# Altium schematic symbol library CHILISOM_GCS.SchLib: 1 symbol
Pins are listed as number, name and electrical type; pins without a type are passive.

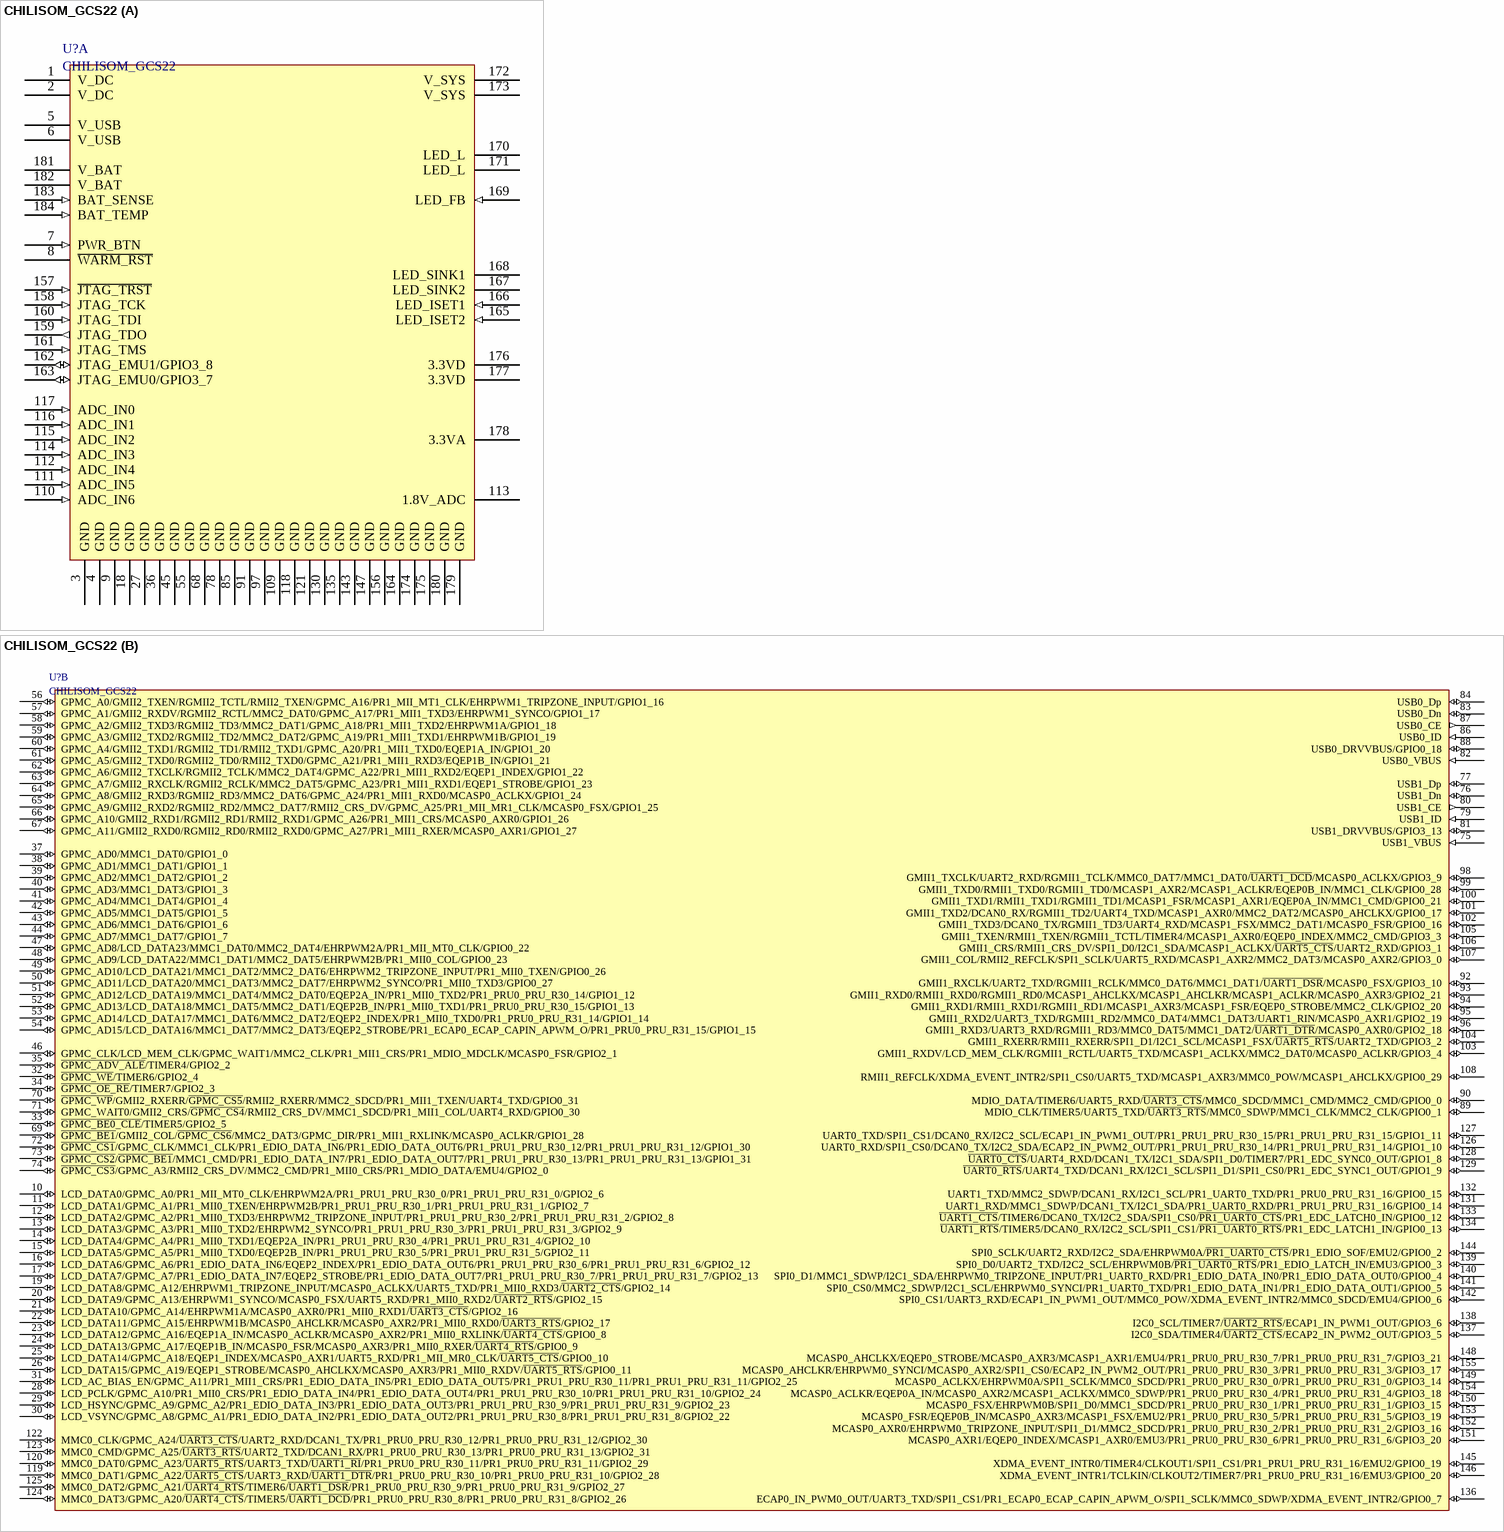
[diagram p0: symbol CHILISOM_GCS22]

## CHILISOM_GCS22
designator U?
footprint CHILISOM_GCS22 (Footprint not found)
part A pins: 1 V_DC (power), 2 V_DC (power), 3 GND (power), 4 GND (power), 5 V_USB (power), 6 V_USB (power), 7 PWR_BTN (in), 8 ~{WARM_RST} (oc), 9 GND (power), 18 GND (power), 27 GND (power), 36 GND (power), 45 GND (power), 55 GND (power), 68 GND (power), 78 GND (power), 85 GND (power), 91 GND (power), 97 GND (power), 109 GND (power), 110 ADC_IN6 (in), 111 ADC_IN5 (in), 112 ADC_IN4 (in), 113 1.8V_ADC (power), 114 ADC_IN3 (in), 115 ADC_IN2 (in), 116 ADC_IN1 (in), 117 ADC_IN0 (in), 118 GND (power), 121 GND (power), 130 GND (power), 135 GND (power), 143 GND (power), 147 GND (power), 156 GND (power), 157 ~{JTAG_TRST} (in), 158 JTAG_TCK (in), 159 JTAG_TDO (out), 160 JTAG_TDI (in), 161 JTAG_TMS (in), 162 JTAG_EMU1/GPIO3_8 (io), 163 JTAG_EMU0/GPIO3_7 (io), 164 GND (power), 165 LED_ISET2 (in), 166 LED_ISET1 (in), 167 LED_SINK2, 168 LED_SINK1, 169 LED_FB (in), 170 LED_L, 171 LED_L, 172 V_SYS (power), 173 V_SYS (power), 174 GND (power), 175 GND (power), 176 3.3VD (power), 177 3.3VD (power), 178 3.3VA (power), 179 GND (power), 180 GND (power), 181 V_BAT (power), 182 V_BAT (power), 183 BAT_SENSE (in), 184 BAT_TEMP (in)
part B pins: 10 LCD_DATA0/GPMC_A0/PR1_MII_MT0_CLK/EHRPWM2A/PR1_PRU1_PRU_R30_0/PR1_PRU1_PRU_R31_0/GPIO2_6 (io), 11 LCD_DATA1/GPMC_A1/PR1_MII0_TXEN/EHRPWM2B/PR1_PRU1_PRU_R30_1/PR1_PRU1_PRU_R31_1/GPIO2_7 (io), 12 LCD_DATA2/GPMC_A2/PR1_MII0_TXD3/EHRPWM2_TRIPZONE_INPUT/PR1_PRU1_PRU_R30_2/PR1_PRU1_PRU_R31_2/GPIO2_8 (io), 13 LCD_DATA3/GPMC_A3/PR1_MII0_TXD2/EHRPWM2_SYNCO/PR1_PRU1_PRU_R30_3/PR1_PRU1_PRU_R31_3/GPIO2_9 (io), 14 LCD_DATA4/GPMC_A4/PR1_MII0_TXD1/EQEP2A_IN/PR1_PRU1_PRU_R30_4/PR1_PRU1_PRU_R31_4/GPIO2_10 (io), 15 LCD_DATA5/GPMC_A5/PR1_MII0_TXD0/EQEP2B_IN/PR1_PRU1_PRU_R30_5/PR1_PRU1_PRU_R31_5/GPIO2_11 (io), 16 LCD_DATA6/GPMC_A6/PR1_EDIO_DATA_IN6/EQEP2_INDEX/PR1_EDIO_DATA_OUT6/PR1_PRU1_PRU_R30_6/PR1_PRU1_PRU_R31_6/GPIO2_12 (io), 17 LCD_DATA7/GPMC_A7/PR1_EDIO_DATA_IN7/EQEP2_STROBE/PR1_EDIO_DATA_OUT7/PR1_PRU1_PRU_R30_7/PR1_PRU1_PRU_R31_7/GPIO2_13 (io), 19 LCD_DATA8/GPMC_A12/EHRPWM1_TRIPZONE_INPUT/MCASP0_ACLKX/UART5_TXD/PR1_MII0_RXD3/~{UART2_CTS}/GPIO2_14 (io), 20 LCD_DATA9/GPMC_A13/EHRPWM1_SYNCO/MCASP0_FSX/UART5_RXD/PR1_MII0_RXD2/~{UART2_RTS}/GPIO2_15 (io), 21 LCD_DATA10/GPMC_A14/EHRPWM1A/MCASP0_AXR0/PR1_MII0_RXD1/~{UART3_CTS}/GPIO2_16 (io), 22 LCD_DATA11/GPMC_A15/EHRPWM1B/MCASP0_AHCLKR/MCASP0_AXR2/PR1_MII0_RXD0/~{UART3_RTS}/GPIO2_17 (io), 23 LCD_DATA12/GPMC_A16/EQEP1A_IN/MCASP0_ACLKR/MCASP0_AXR2/PR1_MII0_RXLINK/~{UART4_CTS}/GPIO0_8 (io), 24 LCD_DATA13/GPMC_A17/EQEP1B_IN/MCASP0_FSR/MCASP0_AXR3/PR1_MII0_RXER/~{UART4_RTS}/GPIO0_9 (io), 25 LCD_DATA14/GPMC_A18/EQEP1_INDEX/MCASP0_AXR1/UART5_RXD/PR1_MII_MR0_CLK/~{UART5_CTS}/GPIO0_10 (io), 26 LCD_DATA15/GPMC_A19/EQEP1_STROBE/MCASP0_AHCLKX/MCASP0_AXR3/PR1_MII0_RXDV/~{UART5_RTS}/GPIO0_11 (io), 28 LCD_PCLK/GPMC_A10/PR1_MII0_CRS/PR1_EDIO_DATA_IN4/PR1_EDIO_DATA_OUT4/PR1_PRU1_PRU_R30_10/PR1_PRU1_PRU_R31_10/GPIO2_24 (io), 29 LCD_HSYNC/GPMC_A9/GPMC_A2/PR1_EDIO_DATA_IN3/PR1_EDIO_DATA_OUT3/PR1_PRU1_PRU_R30_9/PR1_PRU1_PRU_R31_9/GPIO2_23 (io), 30 LCD_VSYNC/GPMC_A8/GPMC_A1/PR1_EDIO_DATA_IN2/PR1_EDIO_DATA_OUT2/PR1_PRU1_PRU_R30_8/PR1_PRU1_PRU_R31_8/GPIO2_22 (io), 31 LCD_AC_BIAS_EN/GPMC_A11/PR1_MII1_CRS/PR1_EDIO_DATA_IN5/PR1_EDIO_DATA_OUT5/PR1_PRU1_PRU_R30_11/PR1_PRU1_PRU_R31_11/GPIO2_25 (io), 32 ~{GPMC_WE}/TIMER6/GPIO2_4 (io), 33 ~{GPMC_BE0_CLE}/TIMER5/GPIO2_5 (io), 34 ~{GPMC_OE_RE}/TIMER7/GPIO2_3 (io), 35 ~{GPMC_ADV_ALE}/TIMER4/GPIO2_2 (io), 37 GPMC_AD0/MMC1_DAT0/GPIO1_0 (io), 38 GPMC_AD1/MMC1_DAT1/GPIO1_1 (io), 39 GPMC_AD2/MMC1_DAT2/GPIO1_2 (io), 40 GPMC_AD3/MMC1_DAT3/GPIO1_3 (io), 41 GPMC_AD4/MMC1_DAT4/GPIO1_4 (io), 42 GPMC_AD5/MMC1_DAT5/GPIO1_5 (io), 43 GPMC_AD6/MMC1_DAT6/GPIO1_6 (io), 44 GPMC_AD7/MMC1_DAT7/GPIO1_7 (io), 46 GPMC_CLK/LCD_MEM_CLK/GPMC_WAIT1/MMC2_CLK/PR1_MII1_CRS/PR1_MDIO_MDCLK/MCASP0_FSR/GPIO2_1 (io), 47 GPMC_AD8/LCD_DATA23/MMC1_DAT0/MMC2_DAT4/EHRPWM2A/PR1_MII_MT0_CLK/GPIO0_22 (io), 48 GPMC_AD9/LCD_DATA22/MMC1_DAT1/MMC2_DAT5/EHRPWM2B/PR1_MII0_COL/GPIO0_23 (io), 49 GPMC_AD10/LCD_DATA21/MMC1_DAT2/MMC2_DAT6/EHRPWM2_TRIPZONE_INPUT/PR1_MII0_TXEN/GPIO0_26 (io), 50 GPMC_AD11/LCD_DATA20/MMC1_DAT3/MMC2_DAT7/EHRPWM2_SYNCO/PR1_MII0_TXD3/GPIO0_27 (io), 51 GPMC_AD12/LCD_DATA19/MMC1_DAT4/MMC2_DAT0/EQEP2A_IN/PR1_MII0_TXD2/PR1_PRU0_PRU_R30_14/GPIO1_12 (io), 52 GPMC_AD13/LCD_DATA18/MMC1_DAT5/MMC2_DAT1/EQEP2B_IN/PR1_MII0_TXD1/PR1_PRU0_PRU_R30_15/GPIO1_13 (io), 53 GPMC_AD14/LCD_DATA17/MMC1_DAT6/MMC2_DAT2/EQEP2_INDEX/PR1_MII0_TXD0/PR1_PRU0_PRU_R31_14/GPIO1_14 (io), 54 GPMC_AD15/LCD_DATA16/MMC1_DAT7/MMC2_DAT3/EQEP2_STROBE/PR1_ECAP0_ECAP_CAPIN_APWM_O/PR1_PRU0_PRU_R31_15/GPIO1_15 (io), 56 GPMC_A0/GMII2_TXEN/RGMII2_TCTL/RMII2_TXEN/GPMC_A16/PR1_MII_MT1_CLK/EHRPWM1_TRIPZONE_INPUT/GPIO1_16 (io), 57 GPMC_A1/GMII2_RXDV/RGMII2_RCTL/MMC2_DAT0/GPMC_A17/PR1_MII1_TXD3/EHRPWM1_SYNCO/GPIO1_17 (io), 58 GPMC_A2/GMII2_TXD3/RGMII2_TD3/MMC2_DAT1/GPMC_A18/PR1_MII1_TXD2/EHRPWM1A/GPIO1_18 (io), 59 GPMC_A3/GMII2_TXD2/RGMII2_TD2/MMC2_DAT2/GPMC_A19/PR1_MII1_TXD1/EHRPWM1B/GPIO1_19 (io), 60 GPMC_A4/GMII2_TXD1/RGMII2_TD1/RMII2_TXD1/GPMC_A20/PR1_MII1_TXD0/EQEP1A_IN/GPIO1_20 (io), 61 GPMC_A5/GMII2_TXD0/RGMII2_TD0/RMII2_TXD0/GPMC_A21/PR1_MII1_RXD3/EQEP1B_IN/GPIO1_21 (io), 62 GPMC_A6/GMII2_TXCLK/RGMII2_TCLK/MMC2_DAT4/GPMC_A22/PR1_MII1_RXD2/EQEP1_INDEX/GPIO1_22 (io), 63 GPMC_A7/GMII2_RXCLK/RGMII2_RCLK/MMC2_DAT5/GPMC_A23/PR1_MII1_RXD1/EQEP1_STROBE/GPIO1_23 (io), 64 GPMC_A8/GMII2_RXD3/RGMII2_RD3/MMC2_DAT6/GPMC_A24/PR1_MII1_RXD0/MCASP0_ACLKX/GPIO1_24 (io), 65 GPMC_A9/GMII2_RXD2/RGMII2_RD2/MMC2_DAT7/RMII2_CRS_DV/GPMC_A25/PR1_MII_MR1_CLK/MCASP0_FSX/GPIO1_25 (io), 66 GPMC_A10/GMII2_RXD1/RGMII2_RD1/RMII2_RXD1/GPMC_A26/PR1_MII1_CRS/MCASP0_AXR0/GPIO1_26 (io), 67 GPMC_A11/GMII2_RXD0/RGMII2_RD0/RMII2_RXD0/GPMC_A27/PR1_MII1_RXER/MCASP0_AXR1/GPIO1_27 (io), 69 ~{GPMC_BE1}/GMII2_COL/~{GPMC_CS6}/MMC2_DAT3/GPMC_DIR/PR1_MII1_RXLINK/MCASP0_ACLKR/GPIO1_28 (io), 70 ~{GPMC_WP}/GMII2_RXERR/~{GPMC_CS5}/RMII2_RXERR/MMC2_SDCD/PR1_MII1_TXEN/UART4_TXD/GPIO0_31 (io), 71 GPMC_WAIT0/GMII2_CRS/~{GPMC_CS4}/RMII2_CRS_DV/MMC1_SDCD/PR1_MII1_COL/UART4_RXD/GPIO0_30 (io), 72 ~{GPMC_CS1}/GPMC_CLK/MMC1_CLK/PR1_EDIO_DATA_IN6/PR1_EDIO_DATA_OUT6/PR1_PRU1_PRU_R30_12/PR1_PRU1_PRU_R31_12/GPIO1_30 (io), 73 ~{GPMC_CS2}/~{GPMC_BE1}/MMC1_CMD/PR1_EDIO_DATA_IN7/PR1_EDIO_DATA_OUT7/PR1_PRU1_PRU_R30_13/PR1_PRU1_PRU_R31_13/GPIO1_31 (io), 74 ~{GPMC_CS3}/GPMC_A3/RMII2_CRS_DV/MMC2_CMD/PR1_MII0_CRS/PR1_MDIO_DATA/EMU4/GPIO2_0 (io), 75 USB1_VBUS (in), 76 USB1_Dn (io), 77 USB1_Dp (io), 79 USB1_ID (in), 80 USB1_CE (out), 81 USB1_DRVVBUS/GPIO3_13 (io), 82 USB0_VBUS (in), 83 USB0_Dn (io), 84 USB0_Dp (io), 86 USB0_ID (in), 87 USB0_CE (out), 88 USB0_DRVVBUS/GPIO0_18 (io), 89 MDIO_CLK/TIMER5/UART5_TXD/~{UART3_RTS}/MMC0_SDWP/MMC1_CLK/MMC2_CLK/GPIO0_1 (io), 90 MDIO_DATA/TIMER6/UART5_RXD/~{UART3_CTS}/MMC0_SDCD/MMC1_CMD/MMC2_CMD/GPIO0_0 (io), 92 GMII1_RXCLK/UART2_TXD/RGMII1_RCLK/MMC0_DAT6/MMC1_DAT1/~{UART1_DSR}/MCASP0_FSX/GPIO3_10 (io), 93 GMII1_RXD0/RMII1_RXD0/RGMII1_RD0/MCASP1_AHCLKX/MCASP1_AHCLKR/MCASP1_ACLKR/MCASP0_AXR3/GPIO2_21 (io), 94 GMII1_RXD1/RMII1_RXD1/RGMII1_RD1/MCASP1_AXR3/MCASP1_FSR/EQEP0_STROBE/MMC2_CLK/GPIO2_20 (io), 95 GMII1_RXD2/UART3_TXD/RGMII1_RD2/MMC0_DAT4/MMC1_DAT3/UART1_RIN/MCASP0_AXR1/GPIO2_19 (io), 96 GMII1_RXD3/UART3_RXD/RGMII1_RD3/MMC0_DAT5/MMC1_DAT2/~{UART1_DTR}/MCASP0_AXR0/GPIO2_18 (io), 98 GMII1_TXCLK/UART2_RXD/RGMII1_TCLK/MMC0_DAT7/MMC1_DAT0/~{UART1_DCD}/MCASP0_ACLKX/GPIO3_9 (io), 99 GMII1_TXD0/RMII1_TXD0/RGMII1_TD0/MCASP1_AXR2/MCASP1_ACLKR/EQEP0B_IN/MMC1_CLK/GPIO0_28 (io), 100 GMII1_TXD1/RMII1_TXD1/RGMII1_TD1/MCASP1_FSR/MCASP1_AXR1/EQEP0A_IN/MMC1_CMD/GPIO0_21 (io), 101 GMII1_TXD2/DCAN0_RX/RGMII1_TD2/UART4_TXD/MCASP1_AXR0/MMC2_DAT2/MCASP0_AHCLKX/GPIO0_17 (io), 102 GMII1_TXD3/DCAN0_TX/RGMII1_TD3/UART4_RXD/MCASP1_FSX/MMC2_DAT1/MCASP0_FSR/GPIO0_16 (io), 103 GMII1_RXDV/LCD_MEM_CLK/RGMII1_RCTL/UART5_TXD/MCASP1_ACLKX/MMC2_DAT0/MCASP0_ACLKR/GPIO3_4 (io), 104 GMII1_RXERR/RMII1_RXERR/SPI1_D1/I2C1_SCL/MCASP1_FSX/~{UART5_RTS}/UART2_TXD/GPIO3_2 (io), 105 GMII1_TXEN/RMII1_TXEN/RGMII1_TCTL/TIMER4/MCASP1_AXR0/EQEP0_INDEX/MMC2_CMD/GPIO3_3 (io), 106 GMII1_CRS/RMII1_CRS_DV/SPI1_D0/I2C1_SDA/MCASP1_ACLKX/~{UART5_CTS}/UART2_RXD/GPIO3_1 (io), 107 GMII1_COL/RMII2_REFCLK/SPI1_SCLK/UART5_RXD/MCASP1_AXR2/MMC2_DAT3/MCASP0_AXR2/GPIO3_0 (io), 108 RMII1_REFCLK/XDMA_EVENT_INTR2/SPI1_CS0/UART5_TXD/MCASP1_AXR3/MMC0_POW/MCASP1_AHCLKX/GPIO0_29 (io), 119 MMC0_DAT1/GPMC_A22/~{UART5_CTS}/UART3_RXD/~{UART1_DTR}/PR1_PRU0_PRU_R30_10/PR1_PRU0_PRU_R31_10/GPIO2_28 (io), 120 MMC0_DAT0/GPMC_A23/~{UART5_RTS}/UART3_TXD/~{UART1_RI}/PR1_PRU0_PRU_R30_11/PR1_PRU0_PRU_R31_11/GPIO2_29 (io), 122 MMC0_CLK/GPMC_A24/~{UART3_CTS}/UART2_RXD/DCAN1_TX/PR1_PRU0_PRU_R30_12/PR1_PRU0_PRU_R31_12/GPIO2_30 (io), 123 MMC0_CMD/GPMC_A25/~{UART3_RTS}/UART2_TXD/DCAN1_RX/PR1_PRU0_PRU_R30_13/PR1_PRU0_PRU_R31_13/GPIO2_31 (io), 124 MMC0_DAT3/GPMC_A20/~{UART4_CTS}/TIMER5/~{UART1_DCD}/PR1_PRU0_PRU_R30_8/PR1_PRU0_PRU_R31_8/GPIO2_26 (io), 125 MMC0_DAT2/GPMC_A21/~{UART4_RTS}/TIMER6/~{UART1_DSR}/PR1_PRU0_PRU_R30_9/PR1_PRU0_PRU_R31_9/GPIO2_27 (io), 126 UART0_RXD/SPI1_CS0/DCAN0_TX/I2C2_SDA/ECAP2_IN_PWM2_OUT/PR1_PRU1_PRU_R30_14/PR1_PRU1_PRU_R31_14/GPIO1_10 (io), 127 UART0_TXD/SPI1_CS1/DCAN0_RX/I2C2_SCL/ECAP1_IN_PWM1_OUT/PR1_PRU1_PRU_R30_15/PR1_PRU1_PRU_R31_15/GPIO1_11 (io), 128 ~{UART0_CTS}/UART4_RXD/DCAN1_TX/I2C1_SDA/SPI1_D0/TIMER7/PR1_EDC_SYNC0_OUT/GPIO1_8 (io), 129 ~{UART0_RTS}/UART4_TXD/DCAN1_RX/I2C1_SCL/SPI1_D1/SPI1_CS0/PR1_EDC_SYNC1_OUT/GPIO1_9 (io), 131 UART1_RXD/MMC1_SDWP/DCAN1_TX/I2C1_SDA/PR1_UART0_RXD/PR1_PRU1_PRU_R31_16/GPIO0_14 (io), 132 UART1_TXD/MMC2_SDWP/DCAN1_RX/I2C1_SCL/PR1_UART0_TXD/PR1_PRU0_PRU_R31_16/GPIO0_15 (io), 133 ~{UART1_CTS}/TIMER6/DCAN0_TX/I2C2_SDA/SPI1_CS0/~{PR1_UART0_CTS}/PR1_EDC_LATCH0_IN/GPIO0_12 (io), 134 ~{UART1_RTS}/TIMER5/DCAN0_RX/I2C2_SCL/SPI1_CS1/~{PR1_UART0_RTS}/PR1_EDC_LATCH1_IN/GPIO0_13 (io), 136 ECAP0_IN_PWM0_OUT/UART3_TXD/SPI1_CS1/PR1_ECAP0_ECAP_CAPIN_APWM_O/SPI1_SCLK/MMC0_SDWP/XDMA_EVENT_INTR2/GPIO0_7 (io), 137 I2C0_SDA/TIMER4/~{UART2_CTS}/ECAP2_IN_PWM2_OUT/GPIO3_5 (io), 138 I2C0_SCL/TIMER7/~{UART2_RTS}/ECAP1_IN_PWM1_OUT/GPIO3_6 (io), 139 SPI0_D0/UART2_TXD/I2C2_SCL/EHRPWM0B/~{PR1_UART0_RTS}/PR1_EDIO_LATCH_IN/EMU3/GPIO0_3 (io), 140 SPI0_D1/MMC1_SDWP/I2C1_SDA/EHRPWM0_TRIPZONE_INPUT/PR1_UART0_RXD/PR1_EDIO_DATA_IN0/PR1_EDIO_DATA_OUT0/GPIO0_4 (io), 141 SPI0_CS0/MMC2_SDWP/I2C1_SCL/EHRPWM0_SYNCI/PR1_UART0_TXD/PR1_EDIO_DATA_IN1/PR1_EDIO_DATA_OUT1/GPIO0_5 (io), 142 SPI0_CS1/UART3_RXD/ECAP1_IN_PWM1_OUT/MMC0_POW/XDMA_EVENT_INTR2/MMC0_SDCD/EMU4/GPIO0_6 (io), 144 SPI0_SCLK/UART2_RXD/I2C2_SDA/EHRPWM0A/~{PR1_UART0_CTS}/PR1_EDIO_SOF/EMU2/GPIO0_2 (io), 145 XDMA_EVENT_INTR0/TIMER4/CLKOUT1/SPI1_CS1/PR1_PRU1_PRU_R31_16/EMU2/GPIO0_19 (io), 146 XDMA_EVENT_INTR1/TCLKIN/CLKOUT2/TIMER7/PR1_PRU0_PRU_R31_16/EMU3/GPIO0_20 (io), 148 MCASP0_AHCLKX/EQEP0_STROBE/MCASP0_AXR3/MCASP1_AXR1/EMU4/PR1_PRU0_PRU_R30_7/PR1_PRU0_PRU_R31_7/GPIO3_21 (io), 149 MCASP0_ACLKX/EHRPWM0A/SPI1_SCLK/MMC0_SDCD/PR1_PRU0_PRU_R30_0/PR1_PRU0_PRU_R31_0/GPIO3_14 (io), 150 MCASP0_FSX/EHRPWM0B/SPI1_D0/MMC1_SDCD/PR1_PRU0_PRU_R30_1/PR1_PRU0_PRU_R31_1/GPIO3_15 (io), 151 MCASP0_AXR1/EQEP0_INDEX/MCASP1_AXR0/EMU3/PR1_PRU0_PRU_R30_6/PR1_PRU0_PRU_R31_6/GPIO3_20 (io), 152 MCASP0_AXR0/EHRPWM0_TRIPZONE_INPUT/SPI1_D1/MMC2_SDCD/PR1_PRU0_PRU_R30_2/PR1_PRU0_PRU_R31_2/GPIO3_16 (io), 153 MCASP0_FSR/EQEP0B_IN/MCASP0_AXR3/MCASP1_FSX/EMU2/PR1_PRU0_PRU_R30_5/PR1_PRU0_PRU_R31_5/GPIO3_19 (io), 154 MCASP0_ACLKR/EQEP0A_IN/MCASP0_AXR2/MCASP1_ACLKX/MMC0_SDWP/PR1_PRU0_PRU_R30_4/PR1_PRU0_PRU_R31_4/GPIO3_18 (io), 155 MCASP0_AHCLKR/EHRPWM0_SYNCI/MCASP0_AXR2/SPI1_CS0/ECAP2_IN_PWM2_OUT/PR1_PRU0_PRU_R30_3/PR1_PRU0_PRU_R31_3/GPIO3_17 (io)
